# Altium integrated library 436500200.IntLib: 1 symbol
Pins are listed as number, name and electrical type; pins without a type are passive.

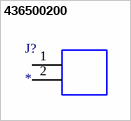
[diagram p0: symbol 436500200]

## 436500200
designator J?
Connector Header Through Hole, Right Angle 2 position 0.118 (3.00mm); MF: Molex; MP: 436500200
footprint CONN_SD-43650-001_02_MOL
pins: 1, 2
